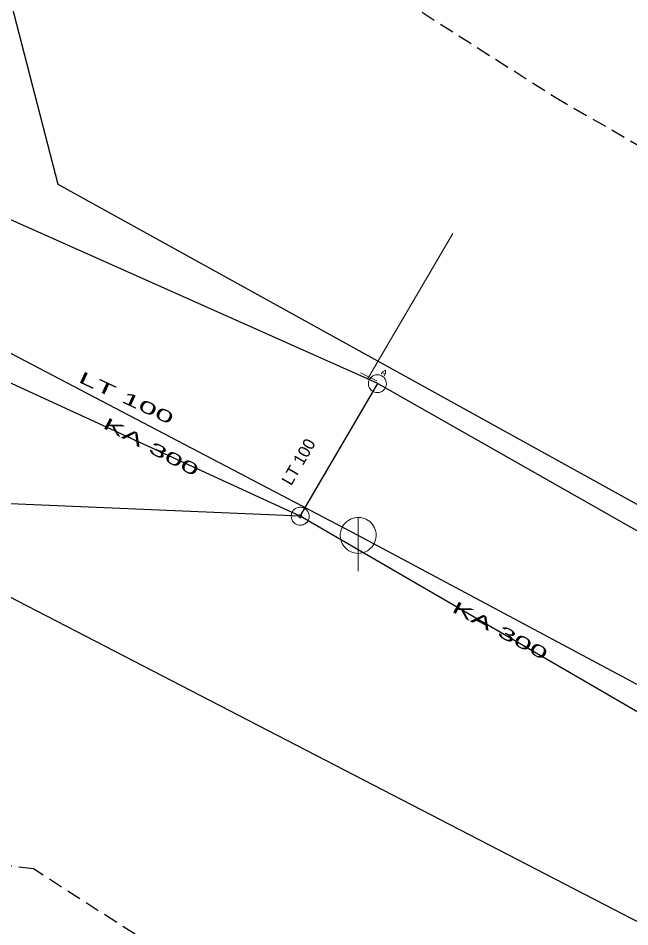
# Model space of a CAD drawing. Extents: x -687593 to -687108, y -975254 to -974717.
# Drawn here: x -687455.8 to -687421.8, y -974927.4 to -974876.8 of the extents above; entities that cross this region are included whole.
import ezdxf
from ezdxf.enums import TextEntityAlignment as Align

# ---------------------------------------------------------------- set-up
doc = ezdxf.new("R2010")
doc.units = 0
doc.header["$LTSCALE"] = 0.27
doc.linetypes.add('MEDIUM_DASHED', pattern=[4.5, 3, -1.5])
for name, color, linetype, lineweight in [('1', 7, 'Continuous', 25), ('13', 7, 'Continuous', 13), ('14', 7, 'Continuous', 13), ('17', 7, 'Continuous', 25), ('22', 7, 'Continuous', 13), ('23', 7, 'Continuous', 13), ('34', 7, 'Continuous', 13), ('47', 7, 'Continuous', 13), ('63', 7, 'MEDIUM_DASHED', 25)]:
    doc.layers.add(name, color=color, linetype=linetype, lineweight=lineweight)

msp = doc.modelspace()

# ---------------------------------------------------------------- linework, layer by layer
at = {"layer": '1'}
msp.add_lwpolyline([(-687190.553, -975166.941), (-687164.86, -975177.861), (-687155.924, -975158.837), (-687125.348, -975155.541), (-687124.826, -975139.621), (-687173.065, -975131.89), (-687231.828, -975028.025), (-687222.959, -975015.464), (-687237.898, -975004.026), (-687247.4, -975009.654), (-687276.892, -974983.781), (-687453.606, -974886.044), (-687460.232, -974860.45), (-687474.874, -974858.564), (-687482.889, -974882.272), (-687502.421, -974882.802), (-687499.452, -974907.164), (-687464.42, -974904.824), (-687331.319, -974973.728), (-687252.566, -975037.916), (-687192.379, -975151.48)], close=True, dxfattribs=at)
at = {"layer": '13'}
msp.add_line((-687436.326, -974896.762), (-687431.647, -974888.785), dxfattribs=at)
at = {"layer": '14', "lineweight": 25}
for p, q in [((-687436.91, -974905.59), (-687459.21, -974893.91)), ((-687420.363, -974914.448), (-687436.91, -974905.59))]:
    msp.add_line(p, q, dxfattribs=at)
at = {"layer": '14'}
msp.add_line((-687436.384, -974896.879), (-687436.326, -974896.762), dxfattribs=at)
at = {"layer": '17'}
msp.add_line((-687440.137, -974904.525), (-687435.81, -974897.134), dxfattribs=at)
for points in [[(-687435.81, -974897.134), (-687436.384, -974896.879), (-687476.987, -974878.778), (-687472.749, -974868.359), (-687469.87, -974842.274), (-687463.434, -974780.208), (-687461.035, -974770.463), (-687454.798, -974755.022), (-687445.204, -974742.578), (-687440.405, -974737.48), (-687422.229, -974716.702)], [(-687435.81, -974897.134), (-687294.34, -974977.541), (-687214.33, -974877.654)], [(-687440.137, -974904.525), (-687461.23, -974894.833), (-687480.87, -974891.39), (-687481.12, -974891.28)], [(-687397.965, -974929.018), (-687440.137, -974904.525), (-687515.147, -974901.318)]]:
    msp.add_lwpolyline(points, dxfattribs=at)
at = {"layer": '22'}
msp.add_line((-687436.91, -974907.59), (-687436.909, -974904.59), dxfattribs=at)
msp.add_lwpolyline([(-687435.91, -974905.59), (-687435.915, -974905.481), (-687435.933, -974905.373), (-687435.963, -974905.267), (-687436.003, -974905.166), (-687436.055, -974905.069), (-687436.117, -974904.979), (-687436.189, -974904.896), (-687436.269, -974904.822), (-687436.357, -974904.756), (-687436.451, -974904.701), (-687436.551, -974904.656), (-687436.656, -974904.623), (-687436.763, -974904.601), (-687436.872, -974904.591), (-687436.982, -974904.593), (-687437.09, -974904.607), (-687437.197, -974904.632), (-687437.3, -974904.669), (-687437.398, -974904.718), (-687437.49, -974904.776), (-687437.576, -974904.845), (-687437.653, -974904.922), (-687437.722, -974905.008), (-687437.781, -974905.1), (-687437.829, -974905.198), (-687437.866, -974905.301), (-687437.892, -974905.408), (-687437.906, -974905.516), (-687437.909, -974905.626), (-687437.899, -974905.735), (-687437.878, -974905.842), (-687437.844, -974905.946), (-687437.8, -974906.046), (-687437.745, -974906.141), (-687437.679, -974906.229), (-687437.605, -974906.309), (-687437.522, -974906.381), (-687437.432, -974906.443), (-687437.336, -974906.495), (-687437.234, -974906.536), (-687437.129, -974906.566), (-687437.021, -974906.584), (-687436.911, -974906.59), (-687436.802, -974906.584), (-687436.694, -974906.566), (-687436.589, -974906.537), (-687436.487, -974906.496), (-687436.39, -974906.444), (-687436.3, -974906.382), (-687436.217, -974906.311), (-687436.142, -974906.231), (-687436.077, -974906.143), (-687436.021, -974906.049), (-687435.977, -974905.949), (-687435.943, -974905.845), (-687435.921, -974905.737), (-687435.911, -974905.628)], close=True, dxfattribs=at)
at = {"layer": '23'}
msp.add_line((-687435.408, -974896.618), (-687435.577, -974896.519), dxfattribs=at)
for points in [[(-687435.626, -974896.603), (-687435.551, -974896.474), (-687435.389, -974896.394), (-687435.382, -974896.573), (-687435.457, -974896.702)], [(-687435.407, -974897.39), (-687435.383, -974897.342), (-687435.364, -974897.293), (-687435.352, -974897.243), (-687435.344, -974897.191), (-687435.341, -974897.139), (-687435.345, -974897.086), (-687435.353, -974897.035), (-687435.367, -974896.985), (-687435.386, -974896.936), (-687435.41, -974896.89), (-687435.438, -974896.845), (-687435.472, -974896.804), (-687435.509, -974896.768), (-687435.549, -974896.736), (-687435.592, -974896.707), (-687435.641, -974896.683), (-687435.688, -974896.665), (-687435.741, -974896.652), (-687435.79, -974896.644), (-687435.843, -974896.641), (-687435.897, -974896.645), (-687435.948, -974896.653), (-687435.999, -974896.667), (-687436.048, -974896.685), (-687436.093, -974896.71), (-687436.137, -974896.739), (-687436.177, -974896.772), (-687436.214, -974896.809), (-687436.246, -974896.851), (-687436.275, -974896.894), (-687436.299, -974896.94), (-687436.317, -974896.99), (-687436.331, -974897.041), (-687436.339, -974897.092), (-687436.34, -974897.143), (-687436.337, -974897.196), (-687436.33, -974897.248), (-687436.315, -974897.299), (-687436.296, -974897.347)], [(-687435.741, -974896.652), (-687435.79, -974896.644), (-687435.843, -974896.641), (-687435.897, -974896.645), (-687435.948, -974896.653), (-687435.999, -974896.667), (-687436.048, -974896.685), (-687436.093, -974896.71), (-687436.137, -974896.739), (-687436.177, -974896.772), (-687436.214, -974896.809), (-687436.246, -974896.851), (-687436.275, -974896.894), (-687436.299, -974896.94), (-687436.317, -974896.99), (-687436.331, -974897.041), (-687436.339, -974897.092), (-687436.34, -974897.143), (-687436.337, -974897.196), (-687436.33, -974897.248), (-687436.315, -974897.299), (-687436.296, -974897.347), (-687436.273, -974897.393), (-687436.243, -974897.437), (-687436.212, -974897.478), (-687436.173, -974897.515), (-687436.132, -974897.546), (-687436.089, -974897.575), (-687436.042, -974897.598), (-687435.993, -974897.618), (-687435.942, -974897.631), (-687435.891, -974897.638), (-687435.838, -974897.641), (-687435.787, -974897.639), (-687435.734, -974897.629), (-687435.684, -974897.616), (-687435.636, -974897.597), (-687435.588, -974897.573), (-687435.545, -974897.544), (-687435.504, -974897.511)], [(-687436.296, -974897.347), (-687436.273, -974897.393), (-687436.243, -974897.437), (-687436.212, -974897.478), (-687436.173, -974897.515), (-687436.132, -974897.546), (-687436.089, -974897.575), (-687436.042, -974897.598), (-687435.993, -974897.618), (-687435.942, -974897.631), (-687435.891, -974897.638), (-687435.838, -974897.641), (-687435.787, -974897.639), (-687435.734, -974897.629), (-687435.684, -974897.616), (-687435.636, -974897.597), (-687435.588, -974897.573), (-687435.545, -974897.544), (-687435.504, -974897.511), (-687435.468, -974897.473), (-687435.436, -974897.433), (-687435.407, -974897.39), (-687435.383, -974897.342), (-687435.364, -974897.293), (-687435.352, -974897.243), (-687435.344, -974897.191), (-687435.341, -974897.139), (-687435.345, -974897.086), (-687435.353, -974897.035), (-687435.367, -974896.985), (-687435.386, -974896.936), (-687435.41, -974896.89), (-687435.438, -974896.845), (-687435.472, -974896.804), (-687435.509, -974896.768), (-687435.549, -974896.736), (-687435.592, -974896.707), (-687435.641, -974896.683), (-687435.688, -974896.665), (-687435.741, -974896.652)], [(-687435.504, -974897.511), (-687435.468, -974897.473), (-687435.436, -974897.433), (-687435.407, -974897.39)]]:
    msp.add_lwpolyline(points, dxfattribs=at)
at = {"layer": '34'}
msp.add_line((-687436.774, -974896.54), (-687435.878, -974896.984), dxfattribs=at)
at = {"layer": '47'}
for points in [[(-687439.638, -974904.558), (-687439.637, -974904.506), (-687439.642, -974904.454), (-687439.652, -974904.403), (-687439.667, -974904.353), (-687439.688, -974904.304), (-687439.714, -974904.258), (-687439.744, -974904.216), (-687439.778, -974904.177), (-687439.816, -974904.141), (-687439.858, -974904.109), (-687439.903, -974904.082), (-687439.951, -974904.061), (-687440, -974904.044), (-687440.051, -974904.032), (-687440.103, -974904.026), (-687440.155, -974904.025), (-687440.207, -974904.03), (-687440.259, -974904.04), (-687440.308, -974904.055), (-687440.357, -974904.076), (-687440.403, -974904.102), (-687440.446, -974904.132), (-687440.485, -974904.166), (-687440.521, -974904.204), (-687440.552, -974904.246), (-687440.579, -974904.291), (-687440.601, -974904.339), (-687440.617, -974904.388), (-687440.629, -974904.439), (-687440.635, -974904.491), (-687440.636, -974904.543), (-687440.631, -974904.595), (-687440.622, -974904.647), (-687440.606, -974904.696), (-687440.585, -974904.745), (-687440.56, -974904.791), (-687440.53, -974904.834), (-687440.496, -974904.873), (-687440.457, -974904.909), (-687440.415, -974904.94), (-687440.37, -974904.967), (-687440.323, -974904.989), (-687440.273, -974905.005), (-687440.222, -974905.017), (-687440.17, -974905.023), (-687440.118, -974905.024), (-687440.066, -974905.019), (-687440.015, -974905.01), (-687439.965, -974904.994), (-687439.916, -974904.973), (-687439.87, -974904.948), (-687439.828, -974904.918), (-687439.789, -974904.884), (-687439.753, -974904.845), (-687439.721, -974904.803), (-687439.694, -974904.758), (-687439.673, -974904.711), (-687439.656, -974904.661), (-687439.644, -974904.61)], [(-687440.055, -974904.53), (-687440.054, -974904.521), (-687440.056, -974904.513), (-687440.057, -974904.505), (-687440.059, -974904.497), (-687440.063, -974904.488), (-687440.067, -974904.481), (-687440.072, -974904.474), (-687440.078, -974904.467), (-687440.084, -974904.462), (-687440.091, -974904.456), (-687440.099, -974904.452), (-687440.106, -974904.448), (-687440.114, -974904.446), (-687440.122, -974904.443), (-687440.131, -974904.443), (-687440.14, -974904.442), (-687440.148, -974904.444), (-687440.156, -974904.445), (-687440.164, -974904.447), (-687440.173, -974904.451), (-687440.18, -974904.455), (-687440.187, -974904.46), (-687440.194, -974904.466), (-687440.2, -974904.472), (-687440.205, -974904.479), (-687440.209, -974904.487), (-687440.213, -974904.494), (-687440.215, -974904.502), (-687440.218, -974904.51), (-687440.218, -974904.519), (-687440.219, -974904.528), (-687440.217, -974904.536), (-687440.216, -974904.544), (-687440.214, -974904.552), (-687440.21, -974904.561), (-687440.207, -974904.568), (-687440.201, -974904.575), (-687440.195, -974904.582), (-687440.189, -974904.588), (-687440.182, -974904.593), (-687440.174, -974904.597), (-687440.167, -974904.601), (-687440.159, -974904.603), (-687440.151, -974904.606), (-687440.142, -974904.606), (-687440.133, -974904.607), (-687440.125, -974904.605), (-687440.117, -974904.604), (-687440.109, -974904.602), (-687440.1, -974904.598), (-687440.093, -974904.595), (-687440.086, -974904.589), (-687440.079, -974904.583), (-687440.074, -974904.577), (-687440.068, -974904.57), (-687440.064, -974904.562), (-687440.06, -974904.555), (-687440.058, -974904.547), (-687440.055, -974904.539)]]:
    msp.add_lwpolyline(points, close=True, dxfattribs=at)
at = {"layer": '63'}
msp.add_lwpolyline([(-687526.998, -974914.677), (-687484.572, -974843.781), (-687484.572, -974843.781), (-687425.956, -974881.183), (-687425.956, -974881.183), (-687214.941, -975003.438), (-687214.941, -975003.438), (-687108.316, -975140.766), (-687108.316, -975140.766), (-687138.461, -975189.333), (-687138.461, -975189.333), (-687208.242, -975184.867), (-687208.242, -975184.867), (-687273.556, -975040.84), (-687273.556, -975040.84), (-687454.985, -974924.168), (-687454.985, -974924.168)], close=True, dxfattribs=at)

# ---------------------------------------------------------------- texts
at = {"layer": '1'}
for s, rotation, width, p in [('LT 100', 335, 2.05, (-687449.9539, -974898.2309)), ('LT 100', 335, 2.05, (-687449.9539, -974898.2309)), ('LT 100', 335, 2.05, (-687449.9539, -974898.2309)), ('LT 100', 335, 2.05, (-687449.9539, -974898.2309)), ('LT 100', 335, 2.05, (-687449.9539, -974898.2309)), ('KA 300', 332, 2, (-687448.5915, -974900.9527)), ('KA 300', 332, 2, (-687448.5915, -974900.9527)), ('KA 300', 332, 2, (-687448.5915, -974900.9527)), ('KA 300', 332, 2, (-687448.5915, -974900.9527)), ('KA 300', 332, 2, (-687448.5915, -974900.9527)), ('KA 300', 332, 2, (-687429.1685, -974911.1847)), ('KA 300', 332, 2, (-687429.1685, -974911.1847)), ('KA 300', 332, 2, (-687429.1685, -974911.1847)), ('KA 300', 332, 2, (-687429.1685, -974911.1847)), ('KA 300', 332, 2, (-687429.1685, -974911.1847))]:
    msp.add_text(s, height=0.6667, rotation=rotation, dxfattribs=dict(at, width=width)).set_placement(p, align=Align.CENTER)
msp.add_text('LT 100', height=0.6667, rotation=60, dxfattribs=at).set_placement((-687439.9454, -974901.6581), align=Align.CENTER)
msp.add_text('LT 100', height=0.6667, rotation=60, dxfattribs=at).set_placement((-687439.9454, -974901.6581), align=Align.CENTER)
msp.add_text('LT 100', height=0.6667, rotation=60, dxfattribs=at).set_placement((-687439.9454, -974901.6581), align=Align.CENTER)
msp.add_text('LT 100', height=0.6667, rotation=60, dxfattribs=at).set_placement((-687439.9454, -974901.6581), align=Align.CENTER)
msp.add_text('LT 100', height=0.6667, rotation=60, dxfattribs=at).set_placement((-687439.9454, -974901.6581), align=Align.CENTER)

doc.saveas('drawing.dxf')
